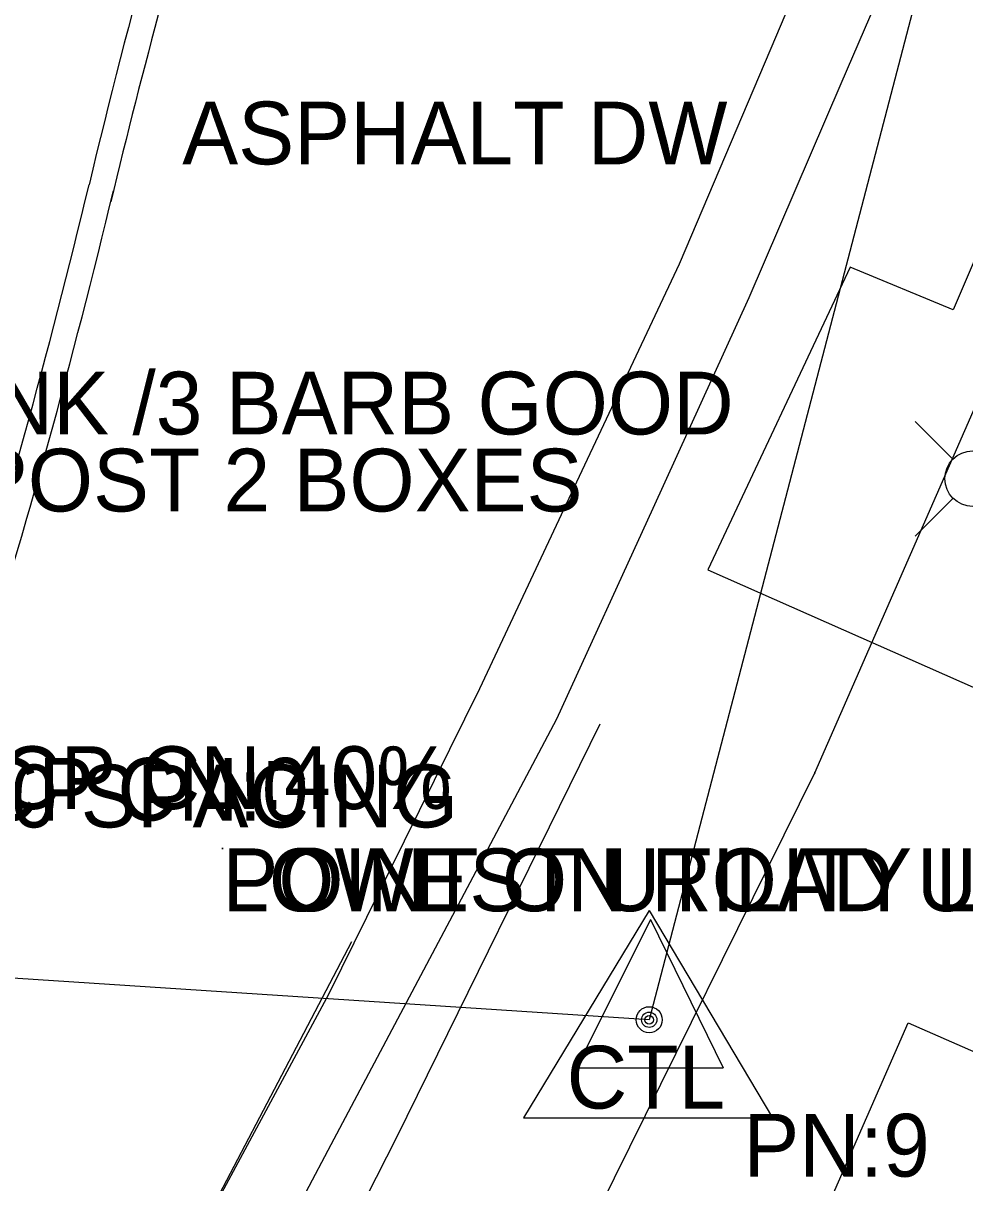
# Model space of a CAD drawing. Extents: x 978516 to 993312, y 1836504 to 1846212.
# Drawn here: x 992419.6 to 992494.6, y 1839656.8 to 1839749.1 of the extents above; entities that cross this region are included whole.
import ezdxf

# ---------------------------------------------------------------- set-up
doc = ezdxf.new("R2010")
doc.units = 0
for name, color, linetype in [('R_MOT Stage 1 Widening', 7, 'Continuous'), ('S_BASELINE', 7, 'Continuous'), ('S_BUILDING', 7, 'Continuous'), ('S_CAL_CORNER', 7, 'Continuous'), ('S_EDGE_PAVEMENT', 7, 'Continuous'), ('S_ELECTRIC_UTILITIES_ANNOT', 7, 'Continuous'), ('S_GAS_UTILITIES', 7, 'Continuous'), ('S_MAILBOX_ANNOT', 7, 'Continuous'), ('S_MANHOLE_ANNOT', 7, 'Continuous'), ('S_PARKING', 7, 'Continuous'), ('S_PRIMARY_CTL', 7, 'Continuous'), ('S_PRIMARY_CTL_ANNOT', 7, 'Continuous'), ('S_SHOULDER', 7, 'Continuous'), ('S_STORM_SEWER_ANNOT', 7, 'Continuous'), ('S_SURVEY_TEXT_ANNOT', 7, 'Continuous'), ('S_UTILITY_POLE', 7, 'Continuous'), ('S_UTL_PT_SYM', 7, 'Continuous')]:
    doc.layers.add(name, color=color, linetype=linetype)

msp = doc.modelspace()

# ---------------------------------------------------------------- linework, layer by layer
at = {"layer": 'R_MOT Stage 1 Widening'}
for centre, radius, start, end in [((992994.732, 1839600.146), 585.958, 158.48261, 166.568057), ((992994.293, 1839598.316), 583.958, 160.04261, 166.472995), ((991880.161, 1839866.331), 559.958, 338.14753, 346.56806), ((991880.161, 1839866.331), 561.958, 338.12484, 346.56806)]:
    msp.add_arc(centre, radius, start, end, dxfattribs=at)
at = {"layer": 'S_BASELINE'}
for p, q in [((992692.912, 1840525.06), (992469.463, 1839669.745)), ((992469.463, 1839669.745), (991863.713, 1839709.338))]:
    msp.add_line(p, q, dxfattribs=at)
at = {"layer": 'S_BUILDING'}
msp.add_lwpolyline([(992540.714, 1839642.443), (992527.522, 1839612.334), (992499.042, 1839624.813), (992498.405, 1839623.361), (992474.477, 1839633.846), (992490.103, 1839669.508), (992528.04, 1839652.886), (992526.242, 1839648.783)], close=True, dxfattribs=at)
at = {"layer": 'S_CAL_CORNER'}
for p, q in [((992469.553, 1839677.726), (992463.676, 1839665.908)), ((992469.553, 1839677.726), (992475.366, 1839665.908)), ((992463.676, 1839665.908), (992475.366, 1839665.908))]:
    msp.add_line(p, q, dxfattribs=at)
at = {"layer": 'S_EDGE_PAVEMENT'}
for points in [[(992486.449, 1839764.306), (992479.152, 1839747.128), (992471.856, 1839729.95), (992463.887, 1839713.036), (992455.918, 1839696.121), (992449.919, 1839683.959), (992443.921, 1839671.798), (992435.559, 1839656.271), (992427.198, 1839640.744), (992417.551, 1839623.511), (992407.904, 1839606.278), (992399.071, 1839591.886), (992390.238, 1839577.495), (992378.177, 1839558.495)], [(992125.945, 1839247.947), (992156.547, 1839280.225), (992195.711, 1839322.733), (992227.568, 1839358.269), (992265.183, 1839402.63), (992286.205, 1839428.389), (992304.406, 1839451.855), (992330.626, 1839487.829), (992352.271, 1839519.016), (992375.556, 1839554.127), (992394.298, 1839584.174), (992413.323, 1839615.728), (992430.801, 1839647.425), (992445.746, 1839675.987)]]:
    msp.add_lwpolyline(points, dxfattribs=at)
at = {"layer": 'S_GAS_UTILITIES'}
for p, q in [((992482.659, 1839689.417), (992508.579, 1839748.581)), ((992440.728, 1839604.666), (992482.659, 1839689.417))]:
    msp.add_line(p, q, dxfattribs=at)
at = {"layer": 'S_PARKING'}
msp.add_lwpolyline([(992530.551, 1839766.433), (992517.035, 1839773.376), (992513.855, 1839774.013), (992505.391, 1839753.564), (992493.689, 1839726.307), (992485.475, 1839729.693), (992474.139, 1839705.584), (992502.445, 1839693.082), (992506.16, 1839691.335)], dxfattribs=at)
at = {"layer": 'S_PRIMARY_CTL'}
for p, q in [((992469.463, 1839678.446), (992459.43, 1839661.933)), ((992469.463, 1839678.446), (992479.288, 1839661.933)), ((992459.43, 1839661.933), (992479.288, 1839661.933))]:
    msp.add_line(p, q, dxfattribs=at)
for radius in [1.037, 0.609, 0.344]:
    msp.add_circle((992469.463, 1839669.745), radius, dxfattribs=at)
at = {"layer": 'S_SHOULDER'}
for points in [[(992492.095, 1839761.345), (992484.743, 1839744.296), (992477.391, 1839727.246), (992469.736, 1839710.474), (992462.081, 1839693.702), (992456.084, 1839682.392), (992450.088, 1839671.082), (992444.092, 1839659.772), (992438.096, 1839648.462), (992432.1, 1839637.152), (992426.103, 1839625.842), (992420.107, 1839614.532), (992414.111, 1839603.222), (992405.601, 1839588.836), (992397.091, 1839574.45), (992384.627, 1839554.745)], [(992133.724, 1839244.468), (992175.699, 1839289.228), (992210.378, 1839327.996), (992245.84, 1839367.749), (992270.746, 1839398.194), (992312.986, 1839449.806), (992333.487, 1839478.226), (992357.85, 1839512.34), (992385.38, 1839551.93), (992403.238, 1839580.106), (992420.171, 1839607.989), (992437.747, 1839637.602), (992449.357, 1839660.451), (992465.538, 1839693.328)]]:
    msp.add_lwpolyline(points, dxfattribs=at)
at = {"layer": 'S_UTILITY_POLE'}
for p, q in [((992493.641, 1839714.435), (992490.657, 1839717.419)), ((992493.641, 1839711.257), (992490.657, 1839708.273))]:
    msp.add_line(p, q, dxfattribs=at)
msp.add_circle((992495.238, 1839712.854), 2.208, dxfattribs=at)
at = {"layer": 'S_UTL_PT_SYM'}
for points in [[(992482.659, 1839689.417), (992482.659, 1839689.467), (992482.659, 1839689.417), (992482.609, 1839689.417), (992482.659, 1839689.417), (992482.659, 1839689.367), (992482.659, 1839689.417), (992482.709, 1839689.417)], [(992435.433, 1839683.391), (992435.433, 1839683.441), (992435.433, 1839683.391), (992435.383, 1839683.391), (992435.433, 1839683.391), (992435.433, 1839683.341), (992435.433, 1839683.391), (992435.483, 1839683.391)]]:
    msp.add_lwpolyline(points, dxfattribs=at)

# ---------------------------------------------------------------- texts
at = {"layer": 'S_ELECTRIC_UTILITIES_ANNOT'}
msp.add_text('LOWEST UTILITY LINE', height=5, dxfattribs=at).set_placement((992435.433, 1839678.391))
at = {"layer": 'S_MAILBOX_ANNOT'}
msp.add_text('1 POST 2 BOXES', height=5, dxfattribs=at).set_placement((992409.887, 1839710.238))
at = {"layer": 'S_MANHOLE_ANNOT'}
msp.add_text('3.00X3.00X.0 SPACING', height=5, dxfattribs=at).set_placement((992381.759, 1839685.069))
at = {"layer": 'S_PRIMARY_CTL'}
msp.add_text('CTL', height=5, dxfattribs=at).set_placement((992462.877, 1839662.669))
at = {"layer": 'S_PRIMARY_CTL_ANNOT'}
msp.add_text('PN:9', height=5, dxfattribs=at).set_placement((992476.963, 1839657.245))
at = {"layer": 'S_STORM_SEWER_ANNOT'}
for s, p in [('DI:18" TY:RCP CN:40%', (992382.25, 1839686.527)), ('DI:18" TY:RCP CN:0', (992380.478, 1839685.606))]:
    msp.add_text(s, height=5, dxfattribs=at).set_placement(p)
at = {"layer": 'S_SURVEY_TEXT_ANNOT'}
for s, p in [('ASPHALT DW', (992432.234, 1839737.891)), ("6' CHAINLINK /3 BARB GOOD", (992383.888, 1839716.373)), ('POINT ON ROAD UNDER LOWES', (992435.433, 1839678.391))]:
    msp.add_text(s, height=5, dxfattribs=at).set_placement(p)

doc.saveas('drawing.dxf')
